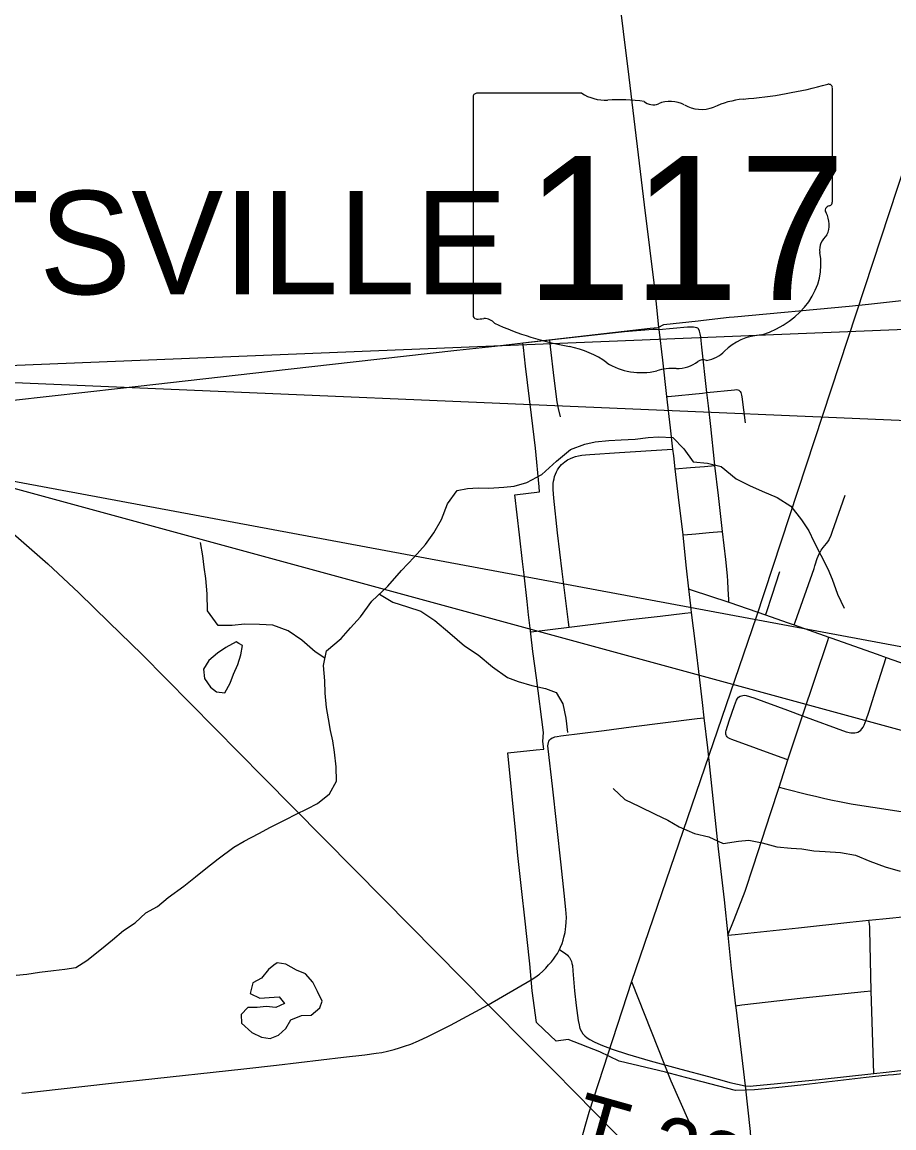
# Model space of a CAD drawing. Extents: x -5.9 to 34, y 0 to 22.
# Drawn here: x 5.923 to 7.523, y 16.281 to 18.309 of the extents above; entities that cross this region are included whole.
import ezdxf

# ---------------------------------------------------------------- set-up
doc = ezdxf.new("R2010")
doc.units = 0
for name, color, linetype in [('GM_X_City_Street', 7, 'Continuous'), ('GM_X_Corporation', 7, 'Continuous'), ('GM_X_Corporation_Text', 7, 'Continuous'), ('GM_X_County_Road', 7, 'Continuous'), ('GM_X_Minor_Lake', 7, 'Continuous'), ('GM_X_Minor_River', 7, 'Continuous'), ('GM_X_Rail_Line', 7, 'Continuous'), ('GM_X_State_Location', 7, 'Continuous'), ('GM_X_State_Route', 7, 'Continuous'), ('GM_X_State_Shield', 7, 'Continuous'), ('GM_X_Township_Road', 7, 'Continuous'), ('GM_X_Township_Road_Text', 7, 'Continuous'), ('GM_X_US_Route', 7, 'Continuous'), ('SH_Text', 7, 'Continuous')]:
    doc.layers.add(name, color=color, linetype=linetype)

msp = doc.modelspace()

# ---------------------------------------------------------------- linework, layer by layer
at = {"layer": 'GM_X_City_Street'}
for points in [[(7.0914, 17.7453), (7.1437, 17.7498), (7.15, 17.7502), (7.1549, 17.75), (7.1578, 17.7497), (7.1605, 17.749), (7.1621, 17.7481), (7.1641, 17.7463)], [(7.2196, 17.2454), (7.2195, 17.2491), (7.2187, 17.2696), (7.218, 17.2837), (7.2173, 17.2932), (7.2143, 17.3235), (7.2083, 17.3748), (7.2006, 17.4406), (7.1941, 17.4957), (7.1934, 17.5026), (7.1865, 17.5672), (7.1824, 17.6051), (7.1797, 17.6295), (7.1705, 17.7127), (7.1693, 17.7252), (7.1684, 17.7319), (7.1674, 17.737), (7.1661, 17.7419), (7.1641, 17.7463)], [(6.9109, 17.585), (6.9071, 17.6004), (6.9048, 17.6128), (6.8994, 17.656), (6.8927, 17.7136), (6.8913, 17.7261)], [(7.1056, 17.6223), (7.1084, 17.6226), (7.1714, 17.6287), (7.1797, 17.6295), (7.2304, 17.6348), (7.2332, 17.6349), (7.2365, 17.6345), (7.2381, 17.6338), (7.2394, 17.6329), (7.2405, 17.6315), (7.2416, 17.6294), (7.2424, 17.6271), (7.2431, 17.6246), (7.2438, 17.6215), (7.2499, 17.5741)], [(6.9266, 17.1995), (6.9255, 17.2087), (6.914, 17.3013), (6.9055, 17.3725), (6.8987, 17.4356), (6.8974, 17.4517), (6.8973, 17.4578), (6.8976, 17.4629), (6.8981, 17.4671), (6.899, 17.4715), (6.9, 17.4756), (6.9016, 17.4798), (6.9034, 17.4841), (6.9055, 17.4876), (6.9081, 17.4915), (6.9106, 17.4947), (6.9127, 17.4975), (6.9158, 17.5), (6.9187, 17.5026), (6.9238, 17.5059), (6.9295, 17.5084), (6.9335, 17.5102), (6.9386, 17.5121), (6.9439, 17.5134), (6.95, 17.5147), (6.9568, 17.5155), (6.9645, 17.5161), (7.0194, 17.5196), (7.1069, 17.5253), (7.1166, 17.526)], [(7.121, 17.4894), (7.1496, 17.4922), (7.1749, 17.4941), (7.1941, 17.4957)], [(7.3396, 17.2033), (7.3415, 17.2086), (7.3761, 17.3071), (7.3775, 17.3118), (7.3792, 17.3174), (7.3804, 17.3215), (7.3817, 17.3251), (7.3835, 17.3294), (7.3855, 17.3337), (7.3877, 17.3378), (7.3894, 17.3405), (7.393, 17.3451), (7.3959, 17.3488), (7.3989, 17.353), (7.4031, 17.3585), (7.4047, 17.3618), (7.4067, 17.3662), (7.4101, 17.3752), (7.4251, 17.4187), (7.4331, 17.4411)], [(7.1352, 17.3686), (7.1369, 17.3687), (7.1593, 17.3706), (7.1837, 17.3728), (7.2061, 17.3747), (7.2083, 17.3748)], [(7.2872, 17.2217), (7.2888, 17.2263), (7.2995, 17.258), (7.3132, 17.3016)], [(7.1457, 17.2694), (7.1509, 17.2677), (7.2196, 17.2454), (7.2217, 17.2447), (7.2872, 17.2217), (7.327, 17.2077), (7.3396, 17.2033), (7.4035, 17.181), (7.4067, 17.1799), (7.4921, 17.1497), (7.5083, 17.1437)], [(6.8571, 17.1906), (6.9266, 17.1995), (7.0388, 17.2134), (7.0935, 17.2196), (7.1391, 17.2247), (7.1507, 17.226)], [(7.2179, 16.6343), (7.2298, 16.663), (7.2495, 16.7151), (7.265, 16.7618), (7.2963, 16.8573), (7.3121, 16.9057), (7.3283, 16.9558), (7.3404, 16.9929), (7.355, 17.0365), (7.4013, 17.1745), (7.4035, 17.181)], [(7.4593, 17.0084), (7.4617, 17.0102), (7.464, 17.0126), (7.4662, 17.0158), (7.4683, 17.0197), (7.4717, 17.0293), (7.4764, 17.0436), (7.4895, 17.0841), (7.5083, 17.1437)], [(7.3283, 16.9558), (7.3157, 16.9604), (7.2256, 16.9933), (7.222, 16.9947), (7.2188, 16.9965), (7.2166, 16.9981), (7.2153, 16.9997), (7.2148, 17.001), (7.2141, 17.0032), (7.214, 17.0054), (7.2141, 17.0073), (7.2147, 17.0096), (7.2206, 17.0272), (7.2299, 17.0554), (7.2339, 17.0654), (7.2358, 17.0685), (7.2375, 17.0707), (7.2403, 17.0726), (7.2428, 17.0736)], [(7.2428, 17.0736), (7.2457, 17.0742), (7.2488, 17.0743), (7.2519, 17.0741), (7.2659, 17.0694), (7.3275, 17.0468), (7.355, 17.0365), (7.435, 17.0072), (7.4439, 17.0052), (7.4478, 17.0052), (7.4512, 17.0053), (7.4541, 17.0058), (7.4566, 17.0068), (7.4593, 17.0084)], [(6.8912, 16.9925), (6.8931, 16.9946), (6.8958, 16.9962), (6.898, 16.9971), (6.9003, 16.9979), (6.9049, 16.9989), (6.9117, 16.9998), (6.9912, 17.0099), (7.0406, 17.0162), (7.1619, 17.0317), (7.1741, 17.0332)], [(6.9089, 16.6079), (6.9111, 16.6121), (6.9139, 16.6188), (6.9159, 16.625), (6.9173, 16.6308), (6.9192, 16.6391), (6.9202, 16.6453), (6.9208, 16.6503), (6.9214, 16.6584), (6.9217, 16.6666), (6.9216, 16.6743), (6.921, 16.6816), (6.9179, 16.7114), (6.9124, 16.7632), (6.8964, 16.9076), (6.8883, 16.9762), (6.8877, 16.9815), (6.888, 16.9846), (6.8886, 16.9877), (6.8896, 16.99), (6.8912, 16.9925)], [(7.3121, 16.9057), (7.3213, 16.9034), (7.3645, 16.8924), (7.3786, 16.889), (7.3933, 16.8856), (7.4068, 16.8825), (7.426, 16.8787), (7.444, 16.8753), (7.4638, 16.8722), (7.4841, 16.8691), (7.5442, 16.86), (7.5716, 16.8559), (7.5745, 16.8557), (7.5771, 16.8557), (7.5796, 16.8561), (7.5826, 16.8568)], [(7.2179, 16.6343), (7.2312, 16.6357), (7.3475, 16.648), (7.4417, 16.6581), (7.4769, 16.6616), (7.5024, 16.6641), (7.5509, 16.6689), (7.588, 16.6723), (7.6035, 16.6737)], [(7.486, 16.3808), (7.481, 16.5323), (7.4785, 16.6441), (7.4783, 16.6495), (7.4777, 16.6545), (7.4769, 16.6616)], [(7.232, 16.505), (7.2434, 16.5063), (7.3564, 16.5191), (7.4683, 16.5309), (7.481, 16.5323)]]:
    msp.add_lwpolyline(points, dxfattribs=at)
at = {"layer": 'GM_X_Corporation'}
msp.add_lwpolyline([(7.5723, 16.3836), (7.5218, 16.3783), (7.5124, 16.3773), (7.4717, 16.373), (7.3577, 16.3599), (7.3061, 16.3546), (7.267, 16.3506), (7.2321, 16.3494), (7.1405, 16.3731), (7.1033, 16.3829), (7.0184, 16.4035), (6.9829, 16.4206), (6.9247, 16.4431), (6.9028, 16.4397), (6.8805, 16.4614), (6.8669, 16.4739), (6.859, 16.5322), (6.8548, 16.5815), (6.8451, 16.671), (6.8406, 16.7087), (6.8328, 16.7802), (6.8292, 16.8211), (6.8141, 16.9685), (6.866, 16.974), (6.8801, 16.9756), (6.8785, 16.9895), (6.8797, 17.006), (6.8666, 17.1061), (6.8603, 17.1549), (6.8562, 17.1872), (6.8553, 17.1973), (6.8525, 17.2218), (6.8497, 17.2462), (6.8441, 17.2952), (6.8413, 17.3196), (6.8357, 17.3686), (6.8315, 17.4053), (6.8273, 17.442), (6.8724, 17.4475), (6.8715, 17.4568), (6.8648, 17.5278), (6.8576, 17.5878), (6.8541, 17.6179), (6.8505, 17.648), (6.8469, 17.6781), (6.8429, 17.7122), (6.8416, 17.7208), (7.0756, 17.7475), (7.0901, 17.7486), (7.1006, 17.7544), (7.1638, 17.7614), (7.1734, 17.7625), (7.2206, 17.7677), (7.2294, 17.7686), (7.4407, 17.7878), (7.4759, 17.7917), (7.7523, 17.822)], dxfattribs=at)
at = {"layer": 'GM_X_County_Road'}
msp.add_lwpolyline([(7.5083, 17.1437), (7.5835, 17.1172), (7.664, 17.0891), (7.6845, 17.082)], dxfattribs=at)
at = {"layer": 'GM_X_Minor_Lake'}
for points in [[(6.321, 17.1694), (6.3157, 17.1725), (6.2966, 17.1622), (6.2813, 17.1518), (6.2659, 17.1383), (6.2558, 17.1225), (6.2578, 17.105), (6.269, 17.0889)], [(6.269, 17.0889), (6.2795, 17.0804), (6.2953, 17.0786), (6.3047, 17.0967), (6.311, 17.1133), (6.3189, 17.1307), (6.3244, 17.1488), (6.3277, 17.1655), (6.321, 17.1694)], [(6.3851, 16.579), (6.375, 16.5715), (6.3626, 16.5557), (6.3466, 16.5468), (6.3417, 16.5272), (6.359, 16.5185), (6.3765, 16.5198), (6.3947, 16.521), (6.4043, 16.5087), (6.3883, 16.5014), (6.3709, 16.5032), (6.3542, 16.5019), (6.3375, 16.5014), (6.3252, 16.4887), (6.3258, 16.4727), (6.3445, 16.4557), (6.3625, 16.4471), (6.3784, 16.4446), (6.3936, 16.4512), (6.4067, 16.4631), (6.416, 16.4789)], [(6.416, 16.4789), (6.4359, 16.487), (6.4533, 16.4875), (6.4694, 16.5009), (6.4734, 16.513), (6.4653, 16.5313), (6.4565, 16.5482), (6.4431, 16.5636), (6.4265, 16.5699), (6.4069, 16.5809), (6.3911, 16.5834), (6.3851, 16.579)]]:
    msp.add_lwpolyline(points, dxfattribs=at)
at = {"layer": 'GM_X_Minor_River'}
for points in [[(5.9119, 16.5611), (5.9316, 16.563), (5.9551, 16.5664), (5.9809, 16.5698), (6.0014, 16.5717), (6.0219, 16.5751), (6.0418, 16.5877), (6.0686, 16.6093), (6.0886, 16.6256), (6.1093, 16.6427), (6.1307, 16.6568), (6.1499, 16.6755), (6.1713, 16.6872), (6.1913, 16.7036), (6.2196, 16.7244), (6.2411, 16.7415), (6.2602, 16.7563), (6.2825, 16.7742), (6.3116, 16.7957), (6.3307, 16.8068), (6.3574, 16.8207), (6.3788, 16.8325), (6.407, 16.8465), (6.4261, 16.856), (6.4459, 16.8663), (6.465, 16.8759), (6.4873, 16.8937), (6.4998, 16.917), (6.4994, 16.9428), (6.4961, 16.9702), (6.4934, 16.9907), (6.4892, 17.0098), (6.485, 17.0311), (6.4815, 17.0517), (6.4789, 17.0783), (6.4786, 17.1011), (6.476, 17.1292), (6.4817, 17.1557), (6.5086, 17.1787), (6.5256, 17.1982), (6.544, 17.2184), (6.565, 17.2469), (6.5942, 17.2744), (6.6189, 17.3029), (6.6427, 17.3275), (6.6635, 17.3507), (6.6783, 17.3725), (6.6923, 17.3965), (6.7034, 17.4252), (6.7212, 17.4499), (6.7402, 17.4534), (6.7598, 17.4546), (6.7795, 17.4542), (6.8068, 17.4561), (6.8258, 17.458), (6.8493, 17.4645), (6.8768, 17.4792), (6.9037, 17.5038), (6.929, 17.5253), (6.9557, 17.5348), (6.9747, 17.539), (6.9997, 17.5416), (7.0224, 17.5427), (7.0482, 17.5438), (7.0717, 17.5472), (7.0906, 17.5484), (7.1171, 17.5472), (7.1372, 17.5264), (7.1542, 17.5026), (7.1806, 17.4998), (7.2055, 17.4941), (7.2332, 17.4716)], [(7.2332, 17.4716), (7.2579, 17.4591), (7.2812, 17.4488), (7.3083, 17.437), (7.3338, 17.4214), (7.353, 17.396), (7.3663, 17.376), (7.3758, 17.3561), (7.3883, 17.3316), (7.4015, 17.3064), (7.4095, 17.2873), (7.4189, 17.2598), (7.4313, 17.2338)], [(6.4788, 17.1421), (6.4605, 17.1537), (6.4366, 17.1754), (6.4112, 17.1925), (6.3833, 17.2029), (6.3584, 17.204), (6.3311, 17.2045), (6.3084, 17.2026), (6.2827, 17.2023), (6.2634, 17.2292), (6.2624, 17.2603), (6.2599, 17.2884), (6.2572, 17.309), (6.2545, 17.3303), (6.2504, 17.3546)], [(6.5786, 17.2598), (6.6035, 17.2454), (6.6299, 17.2367), (6.6547, 17.2286), (6.6802, 17.2115), (6.7078, 17.1883), (6.7347, 17.1651), (6.7601, 17.1487), (6.7863, 17.1262), (6.8139, 17.1068), (6.8335, 17.0996), (6.8584, 17.0924), (6.8832, 17.0866), (6.9028, 17.0795), (6.9153, 17.0588), (6.9209, 17.0321), (6.9235, 17.0063)], [(7.0074, 16.9031), (7.029, 16.883), (7.056, 16.8704), (7.0846, 16.8563), (7.1078, 16.8453), (7.1288, 16.8328), (7.1566, 16.8209), (7.183, 16.8144), (7.2093, 16.8026), (7.2374, 16.8067), (7.2563, 16.8086), (7.2812, 16.8036), (7.3076, 16.7964), (7.3341, 16.7936), (7.3537, 16.7925), (7.3756, 16.7891), (7.3968, 16.788), (7.4248, 16.786), (7.4519, 16.781), (7.4782, 16.7699), (7.5068, 16.7596), (7.5339, 16.7516)]]:
    msp.add_lwpolyline(points, dxfattribs=at)
at = {"layer": 'GM_X_Rail_Line'}
for points in [[(8.6569, 21), (8.5857, 20.9088), (8.513, 20.7995), (8.4462, 20.6951), (8.3598, 20.5123), (8.2981, 20.3347), (8.2297, 20.1139), (7.7274, 18.6082), (7.2699, 17.2177), (7.0415, 16.5495)], [(7.0415, 16.5495), (6.963, 16.3092), (6.9134, 16.1347), (6.8861, 16.02), (6.8674, 15.9094), (6.8568, 15.8119), (6.8493, 15.7081), (6.852, 15.5617), (6.8512, 15.4414), (6.8655, 15.3442), (6.8872, 15.1912), (6.9793, 14.6929), (7.1092, 14)], [(7.0415, 16.5495), (7.1132, 16.3672), (7.2481, 16.0636), (7.4593, 15.532), (7.8977, 14.4706), (8.0854, 14.0203), (8.0937, 14)]]:
    msp.add_lwpolyline(points, dxfattribs=at)
at = {"layer": 'GM_X_State_Route'}
for p, q in [((7.091, 17.7493), (7.0914, 17.7453)), ((6.7907, 17.7148), (6.8426, 17.7206))]:
    msp.add_line(p, q, dxfattribs=at)
for points in [[(6.8596, 19.666), (6.8681, 19.6199), (6.8746, 19.5815), (6.8799, 19.5439), (6.9164, 19.2453), (6.9472, 18.9899), (6.9643, 18.8405), (6.9794, 18.7171), (6.9986, 18.5492), (7.0031, 18.5029), (7.0153, 18.376), (7.0362, 18.2082), (7.0644, 17.9738), (7.0839, 17.8159), (7.091, 17.7493)], [(6.8426, 17.7206), (6.8913, 17.7261), (6.902, 17.7273), (7.0282, 17.7414), (7.073, 17.7453), (7.081, 17.7457), (7.0868, 17.7456), (7.0914, 17.7453)], [(7.0914, 17.7453), (7.0979, 17.6889), (7.1056, 17.6223)], [(3.7566, 17.3738), (3.9962, 17.401), (4.2161, 17.4254), (4.3756, 17.4435), (4.5763, 17.466), (4.6794, 17.478), (4.773, 17.4892), (5.1549, 17.5316), (5.4721, 17.5669), (5.6415, 17.5845), (5.6627, 17.5867), (5.8415, 17.608), (6.1033, 17.6378), (6.3787, 17.669), (6.5303, 17.6858), (6.7208, 17.707), (6.7907, 17.7148)], [(7.1056, 17.6223), (7.1122, 17.5648), (7.1166, 17.526)], [(7.1166, 17.526), (7.1181, 17.5134), (7.121, 17.4894)], [(7.121, 17.4894), (7.1271, 17.4379), (7.1352, 17.3686)], [(7.1352, 17.3686), (7.1379, 17.3436), (7.1417, 17.3075), (7.1457, 17.2694)], [(7.1457, 17.2694), (7.1492, 17.2382), (7.1507, 17.226)], [(7.1507, 17.226), (7.1578, 17.1684), (7.1658, 17.1026), (7.171, 17.0608), (7.1741, 17.0332)], [(7.1741, 17.0332), (7.1805, 16.9781), (7.1931, 16.862), (7.2001, 16.7928), (7.2111, 16.699), (7.2179, 16.6343)], [(7.2179, 16.6343), (7.2243, 16.573), (7.232, 16.505)], [(7.232, 16.505), (7.2324, 16.5019), (7.2497, 16.3582)], [(7.2497, 16.3582), (7.2604, 16.3575), (7.2644, 16.3577), (7.3856, 16.3698), (7.486, 16.3808), (7.5084, 16.3833), (7.6545, 16.4001), (7.7868, 16.4153)], [(7.2497, 16.3582), (7.2588, 16.2743), (7.2591, 16.2715), (7.2702, 16.1627), (7.2801, 16.0651), (7.2829, 16.0378), (7.2914, 15.9583), (7.2977, 15.8999), (7.3009, 15.8715), (7.3054, 15.8323)]]:
    msp.add_lwpolyline(points, dxfattribs=at)
at = {"layer": 'GM_X_State_Shield'}
for p, q in [((6.9501, 18.1785), (6.757, 18.1785)), ((7.4097, 17.979), (7.4097, 18.1884)), ((6.7505, 18.1716), (6.7505, 17.7713)), ((7.4096, 17.9791), (7.4097, 17.979))]:
    msp.add_line(p, q, dxfattribs=at)
for centre, major_axis, start_param, end_param in [((7.1749, 18.7241), (0.699, 0), 4.814394, 5.042369), ((7.4024, 18.1893), (0.00734, 0), 6.141152, 7.989035), ((6.7581, 18.1724), (0.00764, 0), 1.712693, 3.28349), ((6.996, 18.2249), (0.0741, 0), 4.042523, 4.731795), ((7.0206, 17.9538), (0.2659, 0), 1.404758, 1.657858), ((7.081, 18.1745), (0.0214, 0), 3.836095, 5.185415), ((7.1123, 18.1282), (0.0444, 0), 0.950623, 2.079405), ((7.1697, 18.1917), (0.0534, 0), 4.081561, 5.145723), ((7.2641, 18.0562), (0.1406, 0), 1.699011, 2.107814), ((7.408, 17.9636), (0.0114, 0), 1.883978, 3.671073), ((7.4019, 17.9782), (0.00785, 0), 5.05454, 6.418171), ((7.3358, 17.9372), (0.0682, 0), 5.934695, 6.695948), ((7.436, 17.8914), (0.0496, 0), 2.387724, 3.262537), ((7.2141, 17.8648), (0.1748, 0), 5.101752, 6.440018), ((6.7582, 17.7705), (0.0077, 0), 3.00124, 4.508301), ((6.7593, 17.8114), (0.0588, 0), 4.665946, 4.897461), ((6.7714, 17.7482), (0.0212, 0), 0.519207, 1.627899), ((7.039, 18.1078), (0.5048, 0), 4.195997, 4.488961), ((7.2878, 17.659), (0.0958, 0), 1.647645, 2.488434), ((6.8885, 17.5915), (0.1579, 0), 0.823519, 1.323587), ((7.1246, 17.7163), (0.0534, 0), 4.691044, 5.507374), ((7.1729, 17.6775), (0.015, 0), 1.147584, 2.315152), ((7.1665, 17.7325), (0.0565, 0), 4.937069, 5.64225), ((7.0593, 17.7463), (0.1002, 0), 4.026481, 4.996735), ((7.1172, 17.6079), (0.0824, 0), 1.495662, 1.94098)]:
    msp.add_ellipse(centre, major_axis=major_axis, ratio=0.8, start_param=start_param, end_param=end_param, dxfattribs=at)
at = {"layer": 'GM_X_Township_Road'}
for p, q in [((6.7781, 16.5066), (6.8571, 16.5524)), ((5.9894, 16.3518), (6.0868, 16.3626))]:
    msp.add_line(p, q, dxfattribs=at)
for points in [[(6.8706, 16.5614), (6.8722, 16.5626), (6.8788, 16.5685), (6.8841, 16.5737), (6.8892, 16.5798), (6.8942, 16.5852), (6.8982, 16.5905), (6.902, 16.596), (6.9052, 16.601), (6.9089, 16.6079)], [(6.9089, 16.6079), (6.9155, 16.6039), (6.9201, 16.6005), (6.9235, 16.5975), (6.9255, 16.5953), (6.9274, 16.5932), (6.9289, 16.5911), (6.9301, 16.5886), (6.931, 16.5862), (6.9319, 16.5826), (6.9327, 16.5787), (6.9334, 16.5689), (6.9366, 16.5323), (6.9398, 16.5055), (6.9421, 16.487), (6.9433, 16.4779), (6.9449, 16.4699), (6.9456, 16.4665), (6.9467, 16.4629)], [(6.8571, 16.5524), (6.8658, 16.5578), (6.8706, 16.5614)], [(6.0868, 16.3626), (6.1385, 16.3684), (6.33, 16.3891), (6.3897, 16.3956), (6.5127, 16.4104), (6.5516, 16.4151), (6.5729, 16.4178), (6.583, 16.4194), (6.5936, 16.4217), (6.6059, 16.4248), (6.6156, 16.4278), (6.6246, 16.4306), (6.636, 16.4346), (6.6506, 16.4403), (6.6678, 16.4483), (6.7088, 16.4694), (6.7781, 16.5066)], [(6.9467, 16.4629), (6.9493, 16.4579), (6.9521, 16.4532), (6.9557, 16.4499), (6.96, 16.4463), (6.9647, 16.4431), (6.9727, 16.4388), (6.9849, 16.4332), (7.0056, 16.4253), (7.0339, 16.416), (7.0757, 16.404), (7.132, 16.3887), (7.1824, 16.375), (7.2114, 16.367), (7.2215, 16.3643), (7.2497, 16.3582)], [(5.9223, 16.3447), (5.9298, 16.3452), (5.9894, 16.3518)]]:
    msp.add_lwpolyline(points, dxfattribs=at)
at = {"layer": 'GM_X_US_Route'}
for points in [[(5.6415, 17.5845), (5.7045, 17.5362), (5.7919, 17.4669), (5.8637, 17.4078), (5.9211, 17.3584), (5.9702, 17.3153), (6.027, 17.2622), (6.0827, 17.2079), (6.1425, 17.1497), (6.3662, 16.9237), (6.587, 16.7006), (6.7781, 16.5066), (6.8546, 16.4296), (6.9082, 16.3759), (6.9277, 16.356)], [(6.9277, 16.356), (6.9823, 16.3006), (7.035, 16.247), (7.0526, 16.2296)]]:
    msp.add_lwpolyline(points, dxfattribs=at)
at = {"layer": 'SH_Text'}
for points in [[(9.6717, 17.8317), (5.5354, 17.6641), (9.6717, 17.4879)], [(9.6586, 16.4313), (5.7532, 17.4957), (9.6586, 16.7683)]]:
    msp.add_lwpolyline(points, close=True, dxfattribs=at)

# ---------------------------------------------------------------- texts
at = {"layer": 'GM_X_Corporation_Text'}
msp.add_text('HUNTSVILLE', height=0.18939, rotation=0, dxfattribs=at).set_placement((5.2509, 17.81))
at = {"layer": 'GM_X_State_Location'}
for s in ['s', 'r']:
    msp.add_text(s, height=0.000379, dxfattribs=at).set_placement((7.0727, 17.9448))
msp.add_text('117', height=0.000379, rotation=0, dxfattribs=at).set_placement((6.939, 17.9173))
at = {"layer": 'GM_X_State_Shield'}
msp.add_text('117', height=0.26367, dxfattribs=at).set_placement((6.8462, 17.7996))
at = {"layer": 'GM_X_Township_Road_Text'}
msp.add_text('T-221', height=0.11364, rotation=344.2616, dxfattribs=at).set_placement((6.9257, 16.2374))

doc.saveas('drawing.dxf')
